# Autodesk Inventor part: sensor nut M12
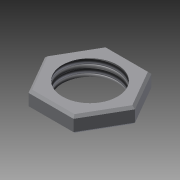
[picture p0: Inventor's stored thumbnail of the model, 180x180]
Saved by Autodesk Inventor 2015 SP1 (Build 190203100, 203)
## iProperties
Created: 2016-05
Part Number: sensor nut M12
Material: Generic
Document SubType Name: Modeling
Designer: Borbon
Density: 1 g/cm^3
Appearance: Default
Mass: 0.46571 g
Surface Area: 5.77215 cm^2
Volume: 0.46571 cm^3
Author: Borbon
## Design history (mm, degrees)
sketch "Sketch1"
  geometry: L1 (4.907, 8.5)-(9.815, 0); L2 (9.815, 0)-(4.907, -8.5); L3 (4.907, -8.5)-(-4.907, -8.5); L4 (-4.907, -8.5)-(-9.815, 0); L5 (-9.815, 0)-(-4.907, 8.5); L6 (-4.907, 8.5)-(4.907, 8.5); C1 r 6 at (0, 0); 2 further points
  constraints: 12 end point, 2 coincident, 1 centre point, 1 horizontal, 13 other
  dimensions: "d0" = 12 diameter of C1; "d1" = 17 distance between parallel lines of L3 L6
extrude "Extrusion1" new body sketch "Sketch1" distance "d2" = 3.5; taper "d3" = 0 deg
chamfer "Chamfer1" distance "d4" = 0.5; stored, may be unused: second distance "d5" = 2, angle "d6" = 45 deg
thread "Thread1" dims "d7" = 10, "d8" = 0
body "Solid1"
